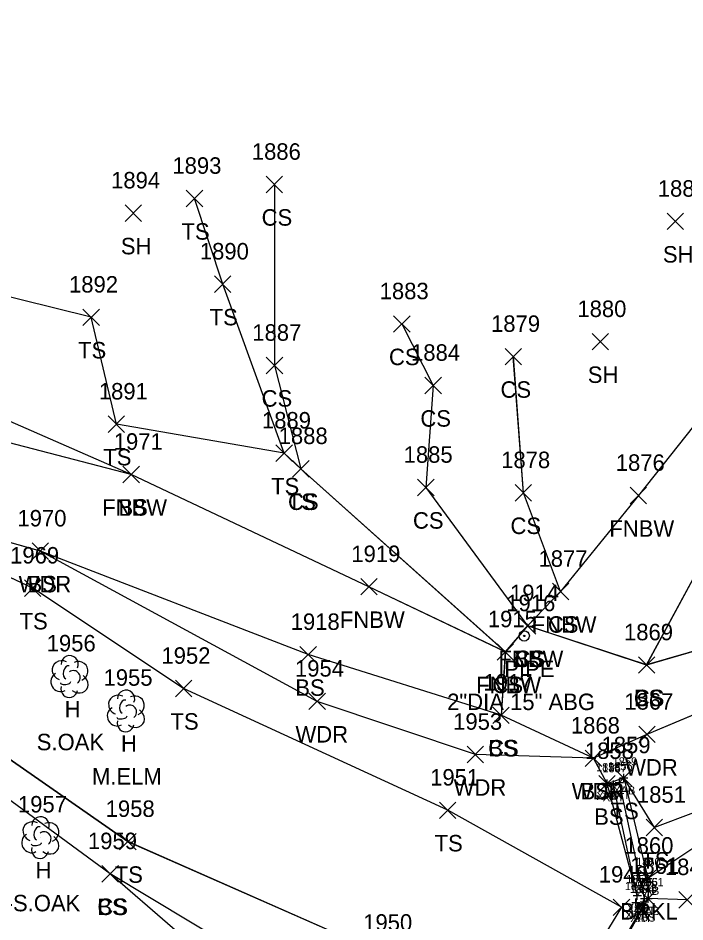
# Model space of a CAD drawing. Extents: x 1415642 to 1422021, y 544543 to 547232.
# Drawn here: x 1416123.6 to 1416204.6, y 546900.4 to 547010.1 of the extents above; entities that cross this region are included whole.
import ezdxf

# ---------------------------------------------------------------- set-up
doc = ezdxf.new("R2010")
doc.units = 0
for name, color, linetype in [('B_A', 7, 'Continuous'), ('B_I', 7, 'Continuous'), ('B_TIC', 7, 'Continuous'), ('BSE', 7, 'Continuous'), ('BSUBM', 7, 'Continuous'), ('L_A', 7, 'Continuous'), ('L_C', 7, 'Continuous'), ('L_I', 7, 'Continuous'), ('L_TIC', 7, 'Continuous'), ('LAWA', 7, 'Continuous'), ('LAWE', 7, 'Continuous'), ('LELB', 7, 'Continuous'), ('LFNC', 7, 'Continuous'), ('LTD', 7, 'Continuous'), ('M_A', 7, 'Continuous'), ('M_C', 7, 'Continuous'), ('M_I', 7, 'Continuous'), ('MPIP', 7, 'Continuous')]:
    doc.layers.add(name, color=color, linetype=linetype)

msp = doc.modelspace()

# ---------------------------------------------------------------- linework, layer by layer
at = {"layer": 'B_TIC'}
for p, q in [((1416197.15, 546917.85), (1416197.22, 546917.85)), ((1416195.12, 546917.16), (1416195.19, 546917.16)), ((1416195.89, 546917.03), (1416195.96, 546917.03)), ((1416195.89, 546917.03), (1416195.96, 546917.03)), ((1416196.61, 546917.29), (1416196.69, 546917.29)), ((1416200.05, 546905.66), (1416200.13, 546905.66)), ((1416198.78, 546903.57), (1416198.85, 546903.57)), ((1416198.78, 546903.57), (1416198.85, 546903.57)), ((1416198.78, 546903.57), (1416198.85, 546903.57)), ((1416199.66, 546903.22), (1416199.73, 546903.22)), ((1416200.1, 546903.2), (1416200.17, 546903.2)), ((1416198.62, 546902.73), (1416198.69, 546902.73)), ((1416199.24, 546902.38), (1416199.32, 546902.38)), ((1416199.58, 546902.42), (1416199.65, 546902.42))]:
    msp.add_line(p, q, dxfattribs=at)
for points in [[(1416195.11, 546916.66), (1416195.11, 546917.66)], [(1416195.88, 546916.53), (1416195.88, 546917.53)], [(1416195.88, 546916.53), (1416195.88, 546917.53)], [(1416196.61, 546916.79), (1416196.61, 546917.79)], [(1416196.64, 546917.85), (1416197.64, 546917.85)], [(1416197.14, 546917.35), (1416197.14, 546918.35)], [(1416194.61, 546917.16), (1416195.61, 546917.16)], [(1416195.38, 546917.03), (1416196.38, 546917.03)], [(1416195.38, 546917.03), (1416196.38, 546917.03)], [(1416196.11, 546917.29), (1416197.11, 546917.29)], [(1416199.55, 546905.66), (1416200.55, 546905.66)], [(1416200.05, 546905.16), (1416200.05, 546906.16)], [(1416198.28, 546903.57), (1416199.28, 546903.57)], [(1416198.28, 546903.57), (1416199.28, 546903.57)], [(1416198.28, 546903.57), (1416199.28, 546903.57)], [(1416198.61, 546902.23), (1416198.61, 546903.23)], [(1416198.78, 546903.07), (1416198.78, 546904.07)], [(1416198.78, 546903.07), (1416198.78, 546904.07)], [(1416198.78, 546903.07), (1416198.78, 546904.07)], [(1416199.16, 546903.22), (1416200.16, 546903.22)], [(1416199.59, 546903.2), (1416200.59, 546903.2)], [(1416199.66, 546902.72), (1416199.66, 546903.72)], [(1416200.09, 546902.7), (1416200.09, 546903.7)], [(1416198.11, 546902.73), (1416199.11, 546902.73)], [(1416198.74, 546902.38), (1416199.74, 546902.38)], [(1416199.07, 546902.42), (1416200.07, 546902.42)], [(1416199.24, 546901.88), (1416199.24, 546902.88)], [(1416199.57, 546901.92), (1416199.57, 546902.92)]]:
    msp.add_lwpolyline(points, dxfattribs=at)
at = {"layer": 'BSE'}
msp.add_lwpolyline([(1416187.5, 546881.78), (1416199.57, 546902.42)], dxfattribs=at)
msp.add_lwpolyline([(1416187.5, 546881.78), (1416199.57, 546902.42)], dxfattribs=at)
at = {"layer": 'BSUBM'}
for points in [[(1416198.78, 546903.57), (1416195.11, 546917.16), (1416197.14, 546917.85), (1416200.05, 546905.66), (1416200.09, 546903.2), (1416187.52, 546880.95), (1416177.37, 546877.17), (1416171.67, 546874.9), (1416171.1, 546875.61), (1416171.51, 546876.27)], [(1416198.78, 546903.57), (1416195.12, 546917.16), (1416197.14, 546917.85), (1416200.05, 546905.66), (1416200.1, 546903.2), (1416187.52, 546880.95), (1416177.38, 546877.17), (1416171.68, 546874.9), (1416171.1, 546875.61), (1416171.52, 546876.27)], [(1416198.78, 546903.57), (1416198.61, 546902.73), (1416199.24, 546902.38), (1416199.66, 546903.22), (1416196.61, 546917.29), (1416195.88, 546917.03)], [(1416198.78, 546903.57), (1416198.61, 546902.73), (1416199.24, 546902.38), (1416199.66, 546903.22), (1416196.61, 546917.28), (1416195.88, 546917.03)], [(1416198.78, 546903.57), (1416195.88, 546917.03)], [(1416198.78, 546903.57), (1416195.88, 546917.03)]]:
    msp.add_lwpolyline(points, dxfattribs=at)
at = {"layer": 'L_TIC'}
for points in [[(1416153.73, 546988.89), (1416155.73, 546990.89)], [(1416155.73, 546988.89), (1416153.73, 546990.89)], [(1416144.04, 546987.19), (1416146.04, 546989.19)], [(1416146.04, 546987.19), (1416144.04, 546989.19)], [(1416136.6, 546985.41), (1416138.6, 546987.41)], [(1416138.6, 546985.41), (1416136.6, 546987.41)], [(1416202.4, 546984.41), (1416204.4, 546986.41)], [(1416204.4, 546984.41), (1416202.4, 546986.41)], [(1416147.46, 546976.79), (1416149.46, 546978.79)], [(1416149.46, 546976.79), (1416147.46, 546978.79)], [(1416131.49, 546972.77), (1416133.49, 546974.77)], [(1416133.49, 546972.77), (1416131.49, 546974.77)], [(1416169.2, 546971.96), (1416171.2, 546973.96)], [(1416171.2, 546971.96), (1416169.2, 546973.96)], [(1416193.29, 546969.8), (1416195.29, 546971.8)], [(1416195.29, 546969.8), (1416193.29, 546971.8)], [(1416182.73, 546968), (1416184.73, 546970)], [(1416184.73, 546968), (1416182.73, 546970)], [(1416153.74, 546966.92), (1416155.74, 546968.92)], [(1416155.74, 546966.92), (1416153.74, 546968.92)], [(1416173.01, 546964.49), (1416175.01, 546966.49)], [(1416175.01, 546964.49), (1416173.01, 546966.49)], [(1416134.55, 546959.79), (1416136.55, 546961.79)], [(1416136.55, 546959.79), (1416134.55, 546961.79)], [(1416154.92, 546956.27), (1416156.92, 546958.27)], [(1416156.92, 546956.27), (1416154.92, 546958.27)], [(1416154.92, 546956.27), (1416156.92, 546958.27)], [(1416156.92, 546956.27), (1416154.92, 546958.27)], [(1416156.94, 546954.38), (1416158.94, 546956.38)], [(1416158.94, 546954.38), (1416156.94, 546956.38)], [(1416156.94, 546954.38), (1416158.94, 546956.38)], [(1416158.94, 546954.38), (1416156.94, 546956.38)], [(1416136.35, 546953.69), (1416138.35, 546955.69)], [(1416138.35, 546953.69), (1416136.35, 546955.69)], [(1416136.35, 546953.69), (1416138.35, 546955.69)], [(1416138.35, 546953.69), (1416136.35, 546955.69)], [(1416172.11, 546952.11), (1416174.11, 546954.11)], [(1416174.11, 546952.11), (1416172.11, 546954.11)], [(1416183.95, 546951.46), (1416185.95, 546953.46)], [(1416185.95, 546951.46), (1416183.95, 546953.46)], [(1416197.91, 546951.13), (1416199.91, 546953.13)], [(1416199.91, 546951.13), (1416197.91, 546953.13)], [(1416125.32, 546944.38), (1416127.32, 546946.38)], [(1416127.32, 546944.38), (1416125.32, 546946.38)], [(1416125.32, 546944.38), (1416127.32, 546946.38)], [(1416127.32, 546944.38), (1416125.32, 546946.38)], [(1416124.39, 546939.88), (1416126.39, 546941.88)], [(1416126.39, 546939.88), (1416124.39, 546941.88)], [(1416165.21, 546940.06), (1416167.21, 546942.06)], [(1416167.21, 546940.06), (1416165.21, 546942.06)], [(1416188.48, 546939.48), (1416190.48, 546941.48)], [(1416190.48, 546939.48), (1416188.48, 546941.48)], [(1416188.48, 546939.48), (1416190.48, 546941.48)], [(1416190.48, 546939.48), (1416188.48, 546941.48)], [(1416184.45, 546935.31), (1416186.45, 546937.31)], [(1416186.45, 546935.31), (1416184.45, 546937.31)], [(1416184.45, 546935.31), (1416186.45, 546937.31)], [(1416186.45, 546935.31), (1416184.45, 546937.31)], [(1416184.45, 546935.31), (1416186.45, 546937.31)], [(1416186.45, 546935.31), (1416184.45, 546937.31)], [(1416181.76, 546932.14), (1416183.76, 546934.14)], [(1416183.76, 546932.14), (1416181.76, 546934.14)], [(1416181.76, 546932.14), (1416183.76, 546934.14)], [(1416183.76, 546932.14), (1416181.76, 546934.14)], [(1416157.83, 546931.82), (1416159.83, 546933.82)], [(1416159.83, 546931.82), (1416157.83, 546933.82)], [(1416198.92, 546930.56), (1416200.92, 546932.56)], [(1416200.92, 546930.56), (1416198.92, 546932.56)], [(1416198.92, 546930.56), (1416200.92, 546932.56)], [(1416200.92, 546930.56), (1416198.92, 546932.56)], [(1416142.71, 546927.71), (1416144.71, 546929.71)], [(1416144.71, 546927.71), (1416142.71, 546929.71)], [(1416158.93, 546926.15), (1416160.93, 546928.15)], [(1416160.93, 546926.15), (1416158.93, 546928.15)], [(1416181.24, 546924.46), (1416183.24, 546926.46)], [(1416183.24, 546924.46), (1416181.24, 546926.46)], [(1416181.24, 546924.46), (1416183.24, 546926.46)], [(1416183.24, 546924.46), (1416181.24, 546926.46)], [(1416198.95, 546922.14), (1416200.95, 546924.14)], [(1416200.95, 546922.14), (1416198.95, 546924.14)], [(1416178.13, 546919.7), (1416180.13, 546921.7)], [(1416180.13, 546919.7), (1416178.13, 546921.7)], [(1416192.46, 546919.24), (1416194.46, 546921.24)], [(1416194.46, 546919.24), (1416192.46, 546921.24)], [(1416192.46, 546919.24), (1416194.46, 546921.24)], [(1416194.46, 546919.24), (1416192.46, 546921.24)], [(1416196.14, 546916.85), (1416198.14, 546918.85)], [(1416198.14, 546916.85), (1416196.14, 546918.85)], [(1416194.11, 546916.16), (1416196.11, 546918.16)], [(1416196.11, 546916.16), (1416194.11, 546918.16)], [(1416174.77, 546912.93), (1416176.77, 546914.93)], [(1416176.77, 546912.93), (1416174.77, 546914.93)], [(1416199.86, 546910.84), (1416201.86, 546912.84)], [(1416201.86, 546910.84), (1416199.86, 546912.84)], [(1416135.94, 546909.12), (1416137.94, 546911.12)], [(1416137.94, 546909.12), (1416135.94, 546911.12)], [(1416133.8, 546905.21), (1416135.8, 546907.21)], [(1416135.8, 546905.21), (1416133.8, 546907.21)], [(1416133.8, 546905.21), (1416135.8, 546907.21)], [(1416135.8, 546905.21), (1416133.8, 546907.21)], [(1416199.05, 546904.66), (1416201.05, 546906.66)], [(1416201.05, 546904.66), (1416199.05, 546906.66)], [(1416199.09, 546902.2), (1416201.09, 546904.2)], [(1416201.09, 546902.2), (1416199.09, 546904.2)], [(1416203.83, 546902.06), (1416205.83, 546904.06)], [(1416205.83, 546902.06), (1416203.83, 546904.06)], [(1416195.86, 546901.15), (1416197.86, 546903.15)], [(1416197.86, 546901.15), (1416195.86, 546903.15)], [(1416195.86, 546901.15), (1416197.86, 546903.15)], [(1416197.86, 546901.15), (1416195.86, 546903.15)]]:
    msp.add_lwpolyline(points, dxfattribs=at)
at = {"layer": 'LAWA'}
for points in [[(1416240.56, 546960.73), (1416233.2, 546953.27), (1416224.51, 546941.93), (1416214.85, 546929.39), (1416199.95, 546923.14), (1416193.46, 546920.24), (1416179.13, 546920.7), (1416159.93, 546927.15), (1416126.32, 546945.38), (1416100.02, 546952.8), (1416028.43, 546991.66), (1415993.05, 547010.51), (1415954.88, 547028.97)], [(1416240.56, 546960.73), (1416233.2, 546953.27), (1416224.51, 546941.93), (1416214.86, 546929.39), (1416199.95, 546923.14), (1416193.46, 546920.24), (1416179.13, 546920.7), (1416159.93, 546927.15), (1416126.32, 546945.39), (1416100.02, 546952.81), (1416028.43, 546991.66), (1415993.05, 547010.51), (1415954.88, 547028.96)]]:
    msp.add_lwpolyline(points, dxfattribs=at)
at = {"layer": 'LAWE'}
for points in [[(1416243.51, 546958.27), (1416236.85, 546951.22), (1416235.87, 546946.71), (1416243.22, 546945.74), (1416246.93, 546942.94), (1416233.53, 546937.38), (1416224.46, 546929.37), (1416217.07, 546920.04), (1416212.31, 546913.83), (1416200.05, 546905.66)], [(1416243.51, 546958.26), (1416236.85, 546951.23), (1416235.87, 546946.71), (1416243.22, 546945.74), (1416246.94, 546942.94), (1416233.53, 546937.38), (1416224.46, 546929.36), (1416217.07, 546920.04), (1416212.31, 546913.83), (1416200.05, 546905.66)]]:
    msp.add_lwpolyline(points, dxfattribs=at)
at = {"layer": 'LELB'}
for points in [[(1416157.94, 546955.38), (1416155.92, 546957.27), (1416135.55, 546960.79), (1416132.49, 546973.78), (1416110.9, 546979.13), (1416081.52, 546992.2), (1416051.18, 547012.47), (1416023.77, 547025.27), (1415981.89, 547041.76), (1415959.36, 547046.67), (1415931.91, 547061.5), (1415911.94, 547074.57), (1415881.06, 547095.53), (1415867.9, 547121.94)], [(1416157.94, 546955.38), (1416155.92, 546957.27), (1416135.55, 546960.79), (1416132.49, 546973.77), (1416110.9, 546979.12), (1416081.52, 546992.2), (1416051.18, 547012.47), (1416023.76, 547025.27), (1415981.89, 547041.76), (1415959.36, 547046.67), (1415931.91, 547061.5), (1415911.93, 547074.57), (1415881.06, 547095.53), (1415867.9, 547121.93)], [(1416137.35, 546954.69), (1416104.5, 546963.24), (1416061.76, 546976.57), (1416028.43, 546991.66)], [(1416137.36, 546954.69), (1416104.5, 546963.23), (1416061.76, 546976.57), (1416028.43, 546991.66)], [(1416154.73, 546989.89), (1416154.74, 546967.92), (1416157.94, 546955.38), (1416182.76, 546933.14), (1416182.24, 546925.46)], [(1416154.74, 546989.9), (1416154.74, 546967.92), (1416157.94, 546955.38), (1416182.77, 546933.14), (1416182.24, 546925.46)], [(1416155.92, 546957.27), (1416148.46, 546977.79), (1416145.04, 546988.19)], [(1416155.92, 546957.27), (1416148.46, 546977.79), (1416145.04, 546988.19)], [(1416196.86, 546902.15), (1416186.27, 546884.75), (1416170.78, 546892.49), (1416168.29, 546896.31), (1416136.94, 546910.12), (1416109.32, 546929.34), (1416090.97, 546938.6), (1416053.51, 546955.4), (1416024.79, 546978.54)], [(1416196.86, 546902.15), (1416186.28, 546884.75), (1416170.78, 546892.49), (1416168.3, 546896.31), (1416136.94, 546910.11), (1416109.32, 546929.33), (1416090.97, 546938.6), (1416053.51, 546955.39), (1416024.79, 546978.54)], [(1416170.2, 546972.96), (1416174.01, 546965.49), (1416173.11, 546953.11), (1416185.45, 546936.31)], [(1416170.2, 546972.96), (1416174.01, 546965.49), (1416173.12, 546953.11), (1416185.45, 546936.31)], [(1416199.92, 546931.56), (1416207.15, 546944.95), (1416213.92, 546957.51), (1416226.49, 546964.85), (1416236.72, 546971.12)], [(1416199.92, 546931.57), (1416207.15, 546944.94), (1416213.92, 546957.51), (1416226.49, 546964.85), (1416236.72, 546971.12)], [(1416189.48, 546940.48), (1416184.95, 546952.46), (1416183.73, 546969)], [(1416189.48, 546940.48), (1416184.95, 546952.45), (1416183.74, 546969)], [(1416245.02, 546957.4), (1416238.63, 546949.83), (1416245.31, 546946.79), (1416248.3, 546942.01), (1416234.3, 546936.22), (1416224.83, 546928.74), (1416217.95, 546917.68), (1416214.38, 546912.24), (1416204.83, 546903.06), (1416200.09, 546903.2)], [(1416245.02, 546957.4), (1416238.63, 546949.83), (1416245.31, 546946.79), (1416248.31, 546942.01), (1416234.3, 546936.22), (1416224.83, 546928.74), (1416217.94, 546917.68), (1416214.38, 546912.24), (1416204.83, 546903.06), (1416200.1, 546903.2)], [(1416196.86, 546902.15), (1416175.77, 546913.92), (1416143.71, 546928.71), (1416125.4, 546940.89), (1416100.02, 546952.81)], [(1416196.86, 546902.15), (1416175.77, 546913.93), (1416143.71, 546928.71), (1416125.39, 546940.88), (1416100.02, 546952.8)], [(1416233.2, 546953.27), (1416221.3, 546944.68), (1416212.41, 546935.17), (1416199.92, 546931.56), (1416185.45, 546936.31)], [(1416233.2, 546953.27), (1416221.3, 546944.68), (1416212.41, 546935.17), (1416199.92, 546931.57), (1416185.45, 546936.31)], [(1416195.12, 546917.16), (1416193.46, 546920.24), (1416182.24, 546925.46), (1416158.83, 546932.82), (1416126.32, 546945.39)], [(1416195.11, 546917.16), (1416193.46, 546920.24), (1416182.24, 546925.46), (1416158.83, 546932.82), (1416126.32, 546945.38)], [(1416165.05, 546879.99), (1416134.8, 546906.21), (1416107.44, 546926.28), (1416090.97, 546938.6)], [(1416165.05, 546879.99), (1416134.8, 546906.21), (1416107.44, 546926.28), (1416090.97, 546938.6)], [(1416224.46, 546929.37), (1416215.69, 546920.43), (1416210.33, 546915.38), (1416200.86, 546911.84), (1416197.14, 546917.85)], [(1416224.46, 546929.36), (1416215.7, 546920.43), (1416210.34, 546915.38), (1416200.86, 546911.84), (1416197.14, 546917.85)], [(1416186.47, 546882.45), (1416168.84, 546885.75), (1416134.8, 546906.21)], [(1416186.47, 546882.45), (1416168.84, 546885.75), (1416134.8, 546906.21)]]:
    msp.add_lwpolyline(points, dxfattribs=at)
at = {"layer": 'LFNC'}
for points in [[(1416222.81, 546984.04), (1416208.55, 546964.28), (1416198.91, 546952.13), (1416189.48, 546940.48), (1416185.45, 546936.31), (1416182.76, 546933.14), (1416166.21, 546941.06), (1416137.35, 546954.69), (1416104.96, 546968.84)], [(1416222.81, 546984.03), (1416208.55, 546964.28), (1416198.92, 546952.14), (1416189.48, 546940.48), (1416185.45, 546936.31), (1416182.77, 546933.14), (1416166.21, 546941.06), (1416137.36, 546954.69), (1416104.96, 546968.84)]]:
    msp.add_lwpolyline(points, dxfattribs=at)
at = {"layer": 'LTD'}
for p, q in [((1416129.84, 546930.21), (1416129.84, 546930.21)), ((1416129.84, 546930.21), (1416129.84, 546930.21)), ((1416136.68, 546926.04), (1416136.68, 546926.04)), ((1416136.68, 546926.04), (1416136.68, 546926.04)), ((1416126.29, 546910.66), (1416126.29, 546910.66)), ((1416126.29, 546910.66), (1416126.29, 546910.66))]:
    msp.add_line(p, q, dxfattribs=at)
for centre in [(1416129.88, 546931.65), (1416136.73, 546927.47), (1416126.34, 546912.09)]:
    msp.add_arc(centre, 1.05, 335.5272, 180.9563, dxfattribs=at)
for centre, major_axis, ratio, start_param, end_param in [((1416129.05, 546930.88), (1.21, -0.51), 0.895232, 1.570796, 4.712389), ((1416130.88, 546930.8), (-1.14, -0.48), 0.949671, 1.570796, 4.712389), ((1416129.63, 546930.67), (-0.208, -0.792), 0.645439, 3.141593, 6.283185), ((1416130.34, 546930.05), (-0.5, 0.667), 0.989748, 3.141593, 6.283185), ((1416128.75, 546929.5), (0.58, -1.04), 0.959034, 3.141593, 6.283185), ((1416129.38, 546929.46), (-0.625, -0.083), 0.423636, 0, 3.141593), ((1416130.84, 546929.38), (-1.09, 0.79), 0.841452, 1.570796, 4.712389), ((1416129.84, 546928.71), (0.26, 1.06), 0.942809, 1.570796, 4.712389), ((1416135.89, 546926.7), (1.21, -0.51), 0.895232, 1.570796, 4.712389), ((1416136.47, 546926.5), (-0.208, -0.792), 0.645439, 3.141593, 6.283185), ((1416137.72, 546926.62), (-1.14, -0.48), 0.949671, 1.570796, 4.712389), ((1416135.6, 546925.33), (0.58, -1.04), 0.959034, 3.141593, 6.283185), ((1416137.18, 546925.87), (-0.5, 0.667), 0.989748, 3.141593, 6.283185), ((1416136.22, 546925.29), (-0.625, -0.083), 0.423636, 0, 3.141593), ((1416137.68, 546925.2), (-1.09, 0.79), 0.841452, 1.570796, 4.712389), ((1416136.68, 546924.54), (0.26, 1.06), 0.942809, 1.570796, 4.712389), ((1416125.5, 546911.33), (1.21, -0.51), 0.895232, 1.570796, 4.712389), ((1416126.08, 546911.12), (-0.208, -0.792), 0.645439, 3.141593, 6.283185), ((1416127.33, 546911.24), (-1.14, -0.48), 0.949671, 1.570796, 4.712389), ((1416125.21, 546909.95), (0.58, -1.04), 0.959034, 3.141593, 6.283185), ((1416126.79, 546910.49), (-0.5, 0.667), 0.989748, 3.141593, 6.283185), ((1416125.83, 546909.91), (-0.625, -0.083), 0.423636, 0, 3.141593), ((1416127.29, 546909.83), (-1.09, 0.79), 0.841452, 1.570796, 4.712389), ((1416126.29, 546909.16), (0.26, 1.06), 0.942809, 1.570796, 4.712389)]:
    msp.add_ellipse(centre, major_axis=major_axis, ratio=ratio, start_param=start_param, end_param=end_param, dxfattribs=at)
at = {"layer": 'MPIP'}
for radius in [0.625, 0.0833]:
    msp.add_circle((1416185.06, 546935.09), radius, dxfattribs=at)

# ---------------------------------------------------------------- texts
at = {"layer": 'B_A'}
for s, p in [('XAB', (1416195.86, 546915.85)), ('XAB', (1416193.83, 546915.16)), ('XAT', (1416194.59, 546915.03)), ('XAT', (1416194.59, 546915.03)), ('XAT', (1416195.31, 546915.29)), ('XAB', (1416198.77, 546903.66)), ('XAT', (1416197.48, 546901.57)), ('XAT', (1416197.48, 546901.57)), ('XAB', (1416197.5, 546901.57)), ('XAT', (1416198.36, 546901.22)), ('XAB', (1416198.81, 546901.2)), ('XAT', (1416197.32, 546900.73)), ('XAT', (1416197.94, 546900.38)), ('XBS', (1416198.31, 546900.42))]:
    msp.add_text(s, height=1, dxfattribs=at).set_placement(p)
at = {"layer": 'B_I'}
for s, p in [('1858', (1416193.77, 546918.66)), ('1856', (1416195.23, 546918.79)), ('1859', (1416195.79, 546919.35)), ('1857', (1416194.54, 546918.53)), ('1857', (1416194.54, 546918.53)), ('1860', (1416198.64, 546907.16)), ('1852', (1416197.43, 546905.07)), ('1852', (1416197.43, 546905.07)), ('1852', (1416197.43, 546905.07)), ('1855', (1416198.31, 546904.72)), ('1861', (1416199.01, 546904.7)), ('1853', (1416197.27, 546904.23)), ('1854', (1416197.89, 546903.88)), ('1945', (1416198.23, 546903.92))]:
    msp.add_text(s, height=1, dxfattribs=at).set_placement(p)
at = {"layer": 'L_A'}
for s, p in [('CS', (1416153.18, 546984.89)), ('TS', (1416143.45, 546983.19)), ('SH', (1416136.09, 546981.41)), ('SH', (1416201.89, 546980.41)), ('TS', (1416146.87, 546972.79)), ('TS', (1416130.9, 546968.77)), ('CS', (1416168.64, 546967.96)), ('SH', (1416192.77, 546965.8)), ('CS', (1416182.18, 546964)), ('CS', (1416153.18, 546962.92)), ('CS', (1416172.45, 546960.49)), ('TS', (1416133.96, 546955.79)), ('TS', (1416154.33, 546952.27)), ('TS', (1416154.33, 546952.27)), ('FNBW', (1416133.83, 546949.69)), ('BS', (1416135.8, 546949.69)), ('TS', (1416156.35, 546950.38)), ('CS', (1416156.38, 546950.38)), ('CS', (1416171.55, 546948.11)), ('CS', (1416183.39, 546947.46)), ('FNBW', (1416195.39, 546947.13)), ('WDR', (1416123.68, 546940.38)), ('BS', (1416124.76, 546940.38)), ('TS', (1416123.8, 546935.88)), ('FNBW', (1416162.68, 546936.06)), ('FNBW', (1416185.96, 546935.48)), ('CS', (1416187.93, 546935.48)), ('FNBW', (1416181.93, 546931.31)), ('CS', (1416183.89, 546931.31)), ('BS', (1416183.89, 546931.31)), ('BS', (1416157.27, 546927.82)), ('FNBW', (1416179.23, 546928.14)), ('CS', (1416181.2, 546928.14)), ('CS', (1416198.36, 546926.56)), ('BS', (1416198.36, 546926.56)), ('H', (1416129.27, 546925.21)), ('TS', (1416142.12, 546923.71)), ('WDR', (1416157.29, 546922.15)), ('H', (1416136.11, 546921.04)), ('CS', (1416180.68, 546920.46)), ('BS', (1416180.68, 546920.46)), ('WDR', (1416197.31, 546918.14)), ('WDR', (1416176.49, 546915.7)), ('WDR', (1416190.82, 546915.24)), ('BS', (1416191.9, 546915.24)), ('BS', (1416193.55, 546912.16)), ('TS', (1416195.55, 546912.85)), ('TS', (1416174.18, 546908.93)), ('TS', (1416199.27, 546906.84)), ('H', (1416125.73, 546905.66)), ('TS', (1416135.35, 546905.12)), ('CS', (1416133.24, 546901.21)), ('BS', (1416133.24, 546901.21)), ('BRKL', (1416196.7, 546900.66))]:
    msp.add_text(s, height=2, dxfattribs=at).set_placement(p)
at = {"layer": 'L_C'}
for s, p in [('S.OAK', (1416125.88, 546921.21)), ('M.ELM', (1416132.59, 546917.04)), ('3-S.OAK', (1416120.62, 546901.66))]:
    msp.add_text(s, height=2, dxfattribs=at).set_placement(p)
at = {"layer": 'L_I'}
for s, p in [('1886', (1416151.99, 546992.89)), ('1893', (1416142.35, 546991.19)), ('1894', (1416134.91, 546989.41)), ('1881', (1416201.27, 546988.41)), ('1890', (1416145.68, 546980.79)), ('1892', (1416129.8, 546976.77)), ('1883', (1416167.51, 546975.96)), ('1880', (1416191.51, 546973.8)), ('1879', (1416181.03, 546972)), ('1887', (1416152.05, 546970.92)), ('1884', (1416171.32, 546968.49)), ('1891', (1416133.42, 546963.79)), ('1889', (1416153.22, 546960.27)), ('1889', (1416153.22, 546960.27)), ('1888', (1416155.25, 546958.38)), ('1888', (1416155.25, 546958.38)), ('1971', (1416135.23, 546957.69)), ('1971', (1416135.23, 546957.69)), ('1885', (1416170.42, 546956.11)), ('1878', (1416182.26, 546955.46)), ('1876', (1416196.17, 546955.13)), ('1970', (1416123.54, 546948.38)), ('1970', (1416123.54, 546948.38)), ('1919', (1416164.07, 546944.06)), ('1969', (1416122.65, 546943.88)), ('1877', (1416186.79, 546943.48)), ('1877', (1416186.79, 546943.48)), ('1914', (1416183.33, 546939.31)), ('1914', (1416183.33, 546939.31)), ('1914', (1416183.33, 546939.31)), ('1918', (1416156.71, 546935.82)), ('1915', (1416180.64, 546936.14)), ('1915', (1416180.64, 546936.14)), ('1869', (1416197.17, 546934.56)), ('1869', (1416197.17, 546934.56)), ('1956', (1416127.09, 546933.21)), ('1952', (1416141.02, 546931.71)), ('1954', (1416157.23, 546930.15)), ('1955', (1416133.99, 546929.04)), ('1917', (1416180.11, 546928.46)), ('1917', (1416180.11, 546928.46)), ('1867', (1416197.21, 546926.14)), ('1953', (1416176.43, 546923.7)), ('1868', (1416190.72, 546923.24)), ('1868', (1416190.72, 546923.24)), ('1858', (1416192.42, 546920.16)), ('1859', (1416194.44, 546920.85)), ('1951', (1416173.64, 546916.93)), ('1851', (1416198.74, 546914.84)), ('1957', (1416123.6, 546913.66)), ('1958', (1416134.25, 546913.12)), ('1959', (1416132.1, 546909.21)), ('1959', (1416132.1, 546909.21)), ('1860', (1416197.22, 546908.66)), ('1861', (1416197.92, 546906.2)), ('1848', (1416202.13, 546906.06)), ('1946', (1416194.11, 546905.15)), ('1946', (1416194.11, 546905.15)), ('1950', (1416165.51, 546899.31))]:
    msp.add_text(s, height=2, dxfattribs=at).set_placement(p)
at = {"layer": 'M_A'}
msp.add_text('IPIPE', height=2, dxfattribs=at).set_placement((1416181.9, 546930.09))
at = {"layer": 'M_C'}
msp.add_text('2"DIA 15" ABG', height=2, dxfattribs=at).set_placement((1416175.7, 546926.09))
at = {"layer": 'M_I'}
msp.add_text('1916', height=2, dxfattribs=at).set_placement((1416182.88, 546938.09))

doc.saveas('drawing.dxf')
